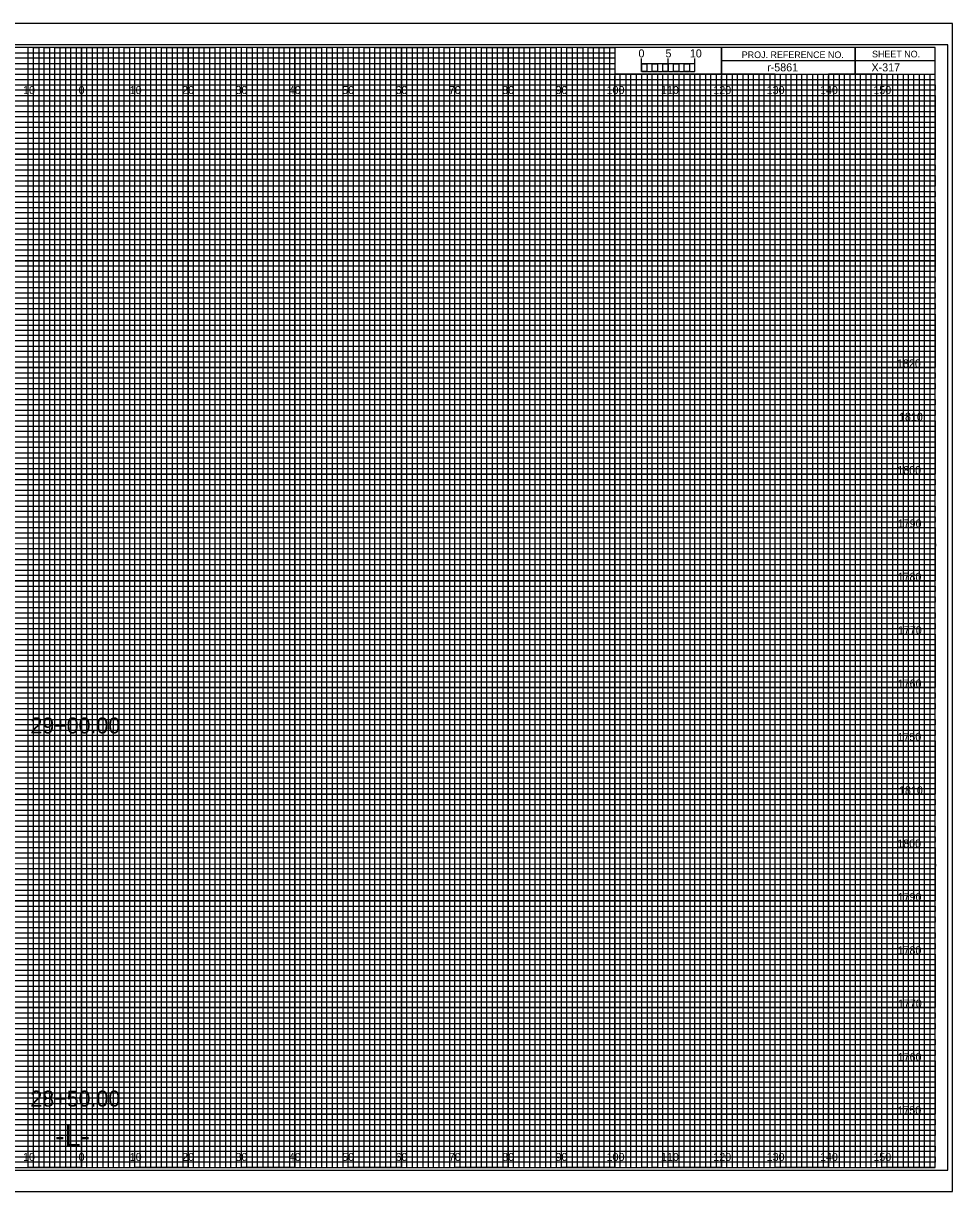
# Model space of a CAD drawing. Extents: x -15 to 323, y -5 to 6170.
# Drawn here: x 149.1 to 323.3, y 2855.5 to 3074.5 of the extents above; entities that cross this region are included whole.
import ezdxf

# ---------------------------------------------------------------- set-up
doc = ezdxf.new("R2010")
doc.units = 0
for name, color, linetype in [('Prop XS Alignment Label', 7, 'Continuous'), ('Prop XS Bar Scale Labels', 7, 'Continuous'), ('Prop XS DDE', 7, 'Continuous'), ('Prop XS DDE Earthwork Shape', 7, 'Continuous'), ('Prop XS DDE Slope Text', 7, 'Continuous'), ('Prop XS DDE Text', 7, 'Continuous'), ('Prop XS Earthwork Shape', 7, 'Continuous'), ('Prop XS Noise Wall', 7, 'Continuous'), ('Prop XS Project Number', 7, 'Continuous'), ('Prop XS Retaining Wall', 7, 'Continuous'), ('Prop XS Station Labels', 7, 'Continuous'), ('Prop XS Temporary Shoring', 7, 'Continuous'), ('Scratch_Level_3', 7, 'Continuous'), ('Scratch_Level_7', 7, 'Continuous'), ('Scratch_Level_8', 7, 'Continuous'), ('Sheet Cross Section Grid Minor 1 CELL', 7, 'Continuous')]:
    doc.layers.add(name, color=color, linetype=linetype)

msp = doc.modelspace()

# ---------------------------------------------------------------- linework, layer by layer
at = {"layer": 'Prop XS Alignment Label'}
for p, q in [((265, 3065.49), (265, 3067.9)), ((265, 3066.9), (265, 3067.9)), ((270, 3065.49), (270, 3067.9)), ((275, 3065.49), (275, 3067.9)), ((275, 3066.9), (275, 3067.9))]:
    msp.add_line(p, q, dxfattribs=at)
for points in [[(275, 3066.9), (265, 3066.9), (265, 3065.49), (275, 3065.49)], [(265, 3066.9), (266, 3066.9), (266, 3065.49), (265, 3065.49)], [(267, 3066.9), (268, 3066.9), (268, 3065.49), (267, 3065.49)], [(269, 3066.9), (270, 3066.9), (270, 3065.49), (269, 3065.49)], [(271, 3066.9), (272, 3066.9), (272, 3065.49), (271, 3065.49)], [(273, 3066.9), (274, 3066.9), (274, 3065.49), (273, 3065.49)]]:
    msp.add_lwpolyline(points, close=True, dxfattribs=at)
at = {"layer": 'Prop XS DDE'}
msp.add_lwpolyline([(-13.4, 2855.5), (323.3, 2855.5), (323.3, 3074.5), (-13.4, 3074.5)], close=True, dxfattribs=at)
at = {"layer": 'Prop XS DDE Slope Text'}
msp.add_lwpolyline([(-10.8, 2859.5), (322.4, 2859.5), (322.4, 3070.5), (-10.8, 3070.5)], close=True, dxfattribs=at)
at = {"layer": 'Prop XS DDE Text'}
for p, q in [((150, 2860), (150, 3070)), ((160, 2860), (160, 3070)), ((170, 2860), (170, 3070)), ((180, 2860), (180, 3070)), ((190, 2860), (190, 3070)), ((200, 2860), (200, 3070)), ((210, 2860), (210, 3070)), ((220, 2860), (220, 3070)), ((230, 2860), (230, 3070)), ((240, 2860), (240, 3070)), ((250, 2860), (250, 3070)), ((260, 2860), (260, 3064.69)), ((270, 2860), (270, 3064.69)), ((280, 2860), (280, 3064.69)), ((290, 2860), (290, 3064.69)), ((300, 2860), (300, 3064.69)), ((310, 2860), (310, 3064.69)), ((0, 3060), (320, 3060)), ((0, 3050), (320, 3050)), ((0, 3040), (320, 3040)), ((0, 3030), (320, 3030)), ((0, 3020), (320, 3020)), ((0, 3010), (320, 3010)), ((0, 3000), (320, 3000)), ((0, 2990), (320, 2990)), ((0, 2980), (320, 2980)), ((0, 2970), (320, 2970)), ((0, 2960), (320, 2960)), ((0, 2950), (320, 2950)), ((0, 2940), (320, 2940)), ((0, 2930), (320, 2930)), ((0, 2920), (320, 2920)), ((0, 2910), (320, 2910)), ((0, 2900), (320, 2900)), ((0, 2890), (320, 2890)), ((0, 2880), (320, 2880)), ((0, 2870), (320, 2870))]:
    msp.add_line(p, q, dxfattribs=at)
at = {"layer": 'Prop XS Earthwork Shape'}
for p, q in [((150, 3070), (140, 3070)), ((150, 2860), (150, 3070)), ((170, 3070), (160, 3070)), ((160, 3070), (160, 2860)), ((170, 2860), (170, 3070)), ((190, 3070), (180, 3070)), ((180, 3070), (180, 2860)), ((190, 2860), (190, 3070)), ((210, 3070), (200, 3070)), ((200, 3070), (200, 2860)), ((210, 2860), (210, 3070)), ((230, 3070), (220, 3070)), ((220, 3070), (220, 2860)), ((230, 2860), (230, 3070)), ((250, 3070), (240, 3070)), ((240, 3070), (240, 2860)), ((250, 2860), (250, 3070)), ((260, 3070), (260, 2860)), ((270, 2860), (270, 3065)), ((290, 3065), (280, 3065)), ((280, 3065), (280, 2860)), ((290, 2860), (290, 3065)), ((310, 3065), (300, 3065)), ((300, 3065), (300, 2860)), ((310, 2860), (310, 3065)), ((160, 2860), (150, 2860)), ((180, 2860), (170, 2860)), ((200, 2860), (190, 2860)), ((220, 2860), (210, 2860)), ((240, 2860), (230, 2860)), ((260, 2860), (250, 2860)), ((280, 2860), (270, 2860)), ((300, 2860), (290, 2860)), ((320, 2860), (310, 2860)), ((320, 2860), (320, 2860))]:
    msp.add_line(p, q, dxfattribs=at)
for points in [[(0, 3060), (320, 3060), (320, 3050), (0, 3050)], [(0, 3040), (320, 3040), (320, 3030), (0, 3030)], [(0, 3020), (320, 3020), (320, 3010), (0, 3010)], [(0, 3000), (320, 3000), (320, 2990), (0, 2990)], [(0, 2980), (320, 2980), (320, 2970), (0, 2970)], [(0, 2960), (320, 2960), (320, 2950), (0, 2950)], [(0, 2940), (320, 2940), (320, 2930), (0, 2930)], [(0, 2920), (320, 2920), (320, 2910), (0, 2910)], [(0, 2900), (320, 2900), (320, 2890), (0, 2890)], [(0, 2880), (320, 2880), (320, 2870), (0, 2870)]]:
    msp.add_lwpolyline(points, dxfattribs=at)
at = {"layer": 'Prop XS Noise Wall'}
for p, q in [((305, 3070), (305, 3065)), ((305, 3065), (305, 3070)), ((280, 3067.5), (280, 3065)), ((320, 3067.49), (280, 3067.49)), ((280, 3065), (320, 3065))]:
    msp.add_line(p, q, dxfattribs=at)
for points in [[(320, 3070), (0, 3070), (0, 2860), (320, 2860)], [(280, 3070), (260, 3070), (260, 3065.03), (280, 3065.03)], [(320, 3070), (280, 3070), (280, 3065), (320, 3065)]]:
    msp.add_lwpolyline(points, close=True, dxfattribs=at)
at = {"layer": 'Prop XS Retaining Wall'}
for p, q in [((267, 3065), (266.01, 3065)), ((266.01, 3065), (266.01, 2860)), ((267, 2860), (267, 3065)), ((269, 3065), (268, 3065)), ((268, 3065), (268, 2860)), ((269, 2860), (269, 3065)), ((266.01, 2860), (265, 2860)), ((268, 2860), (267, 2860))]:
    msp.add_line(p, q, dxfattribs=at)
for points in [[(150, 2860), (151, 2860), (151, 3070), (152, 3070), (152, 2860)], [(152, 2860), (153, 2860), (153, 3070), (154, 3070), (154, 2860)], [(155, 2860), (156, 2860), (156, 3070), (157, 3070), (157, 2860)], [(157, 2860), (158, 2860), (158, 3070), (159, 3070), (159, 2860)], [(160, 2860), (161, 2860), (161, 3070), (162, 3070), (162, 2860)], [(162, 2860), (163, 2860), (163, 3070), (164, 3070), (164, 2860)], [(165, 2860), (166, 2860), (166, 3070), (167, 3070), (167, 2860)], [(167, 2860), (168, 2860), (168, 3070), (169, 3070), (169, 2860)], [(170, 2860), (171, 2860), (171, 3070), (172, 3070), (172, 2860)], [(172, 2860), (173, 2860), (173, 3070), (174, 3070), (174, 2860)], [(175, 2860), (176, 2860), (176, 3070), (177, 3070), (177, 2860)], [(177, 2860), (178, 2860), (178, 3070), (179, 3070), (179, 2860)], [(180, 2860), (181, 2860), (181, 3070), (182, 3070), (182, 2860)], [(182, 2860), (183, 2860), (183, 3070), (184, 3070), (184, 2860)], [(185, 2860), (186, 2860), (186, 3070), (187, 3070), (187, 2860)], [(187, 2860), (188, 2860), (188, 3070), (189, 3070), (189, 2860)], [(190, 2860), (191, 2860), (191, 3070), (192, 3070), (192, 2860)], [(192, 2860), (193, 2860), (193, 3070), (194, 3070), (194, 2860)], [(195, 2860), (196, 2860), (196, 3070), (197, 3070), (197, 2860)], [(197, 2860), (198, 2860), (198, 3070), (199, 3070), (199, 2860)], [(200, 2860), (201, 2860), (201, 3070), (202, 3070), (202, 2860)], [(202, 2860), (203, 2860), (203, 3070), (204, 3070), (204, 2860)], [(205, 2860), (206, 2860), (206, 3070), (207, 3070), (207, 2860)], [(207, 2860), (208, 2860), (208, 3070), (209, 3070), (209, 2860)], [(210, 2860), (211, 2860), (211, 3070), (212, 3070), (212, 2860)], [(212, 2860), (213, 2860), (213, 3070), (214, 3070), (214, 2860)], [(215, 2860), (216, 2860), (216, 3070), (217, 3070), (217, 2860)], [(217, 2860), (218, 2860), (218, 3070), (219, 3070), (219, 2860)], [(220, 2860), (221, 2860), (221, 3070), (222, 3070), (222, 2860)], [(222, 2860), (223, 2860), (223, 3070), (224, 3070), (224, 2860)], [(225, 2860), (226, 2860), (226, 3070), (227, 3070), (227, 2860)], [(227, 2860), (228, 2860), (228, 3070), (229, 3070), (229, 2860)], [(230, 2860), (231, 2860), (231, 3070), (232, 3070), (232, 2860)], [(232, 2860), (233, 2860), (233, 3070), (234, 3070), (234, 2860)], [(235, 2860), (236, 2860), (236, 3070), (237, 3070), (237, 2860)], [(237, 2860), (238, 2860), (238, 3070), (239, 3070), (239, 2860)], [(240, 2860), (241, 2860), (241, 3070), (242, 3070), (242, 2860)], [(242, 2860), (243, 2860), (243, 3070), (244, 3070), (244, 2860)], [(245, 2860), (246, 2860), (246, 3070), (247, 3070), (247, 2860)], [(247, 2860), (248, 2860), (248, 3070), (249, 3070), (249, 2860)], [(250, 2860), (251, 2860), (251, 3070), (252, 3070), (252, 2860)], [(252, 2860), (253, 2860), (253, 3070), (254, 3070), (254, 2860)], [(255, 2860), (256, 2860), (256, 3070), (257, 3070), (257, 2860)], [(257, 2860), (258, 2860), (258, 3070), (259, 3070), (259, 2860)], [(260, 2860), (261, 2860), (261, 3065), (262.02, 3065), (262.02, 2860)], [(262, 2860), (263, 2860), (263, 3065), (263.99, 3065), (263.99, 2860)], [(270, 2860), (270.98, 2860), (270.98, 3065), (272, 3065), (272, 2860)], [(272, 2860), (273, 2860), (273, 3065), (274.05, 3065), (274.05, 2860)], [(275, 2860), (276, 2860), (276, 3065), (277, 3065), (277, 2860)], [(277, 2860), (278, 2860), (278, 3065), (279, 3065), (279, 2860)], [(280, 2860), (281, 2860), (281, 3065), (282, 3065), (282, 2860)], [(282, 2860), (283, 2860), (283, 3065), (284, 3065), (284, 2860)], [(285, 2860), (286, 2860), (286, 3065), (287, 3065), (287, 2860)], [(287, 2860), (288, 2860), (288, 3065), (289, 3065), (289, 2860)], [(290, 2860), (291, 2860), (291, 3065), (292, 3065), (292, 2860)], [(292, 2860), (293, 2860), (293, 3065), (294, 3065), (294, 2860)], [(295, 2860), (296, 2860), (296, 3065), (297, 3065), (297, 2860)], [(297, 2860), (298, 2860), (298, 3065), (299, 3065), (299, 2860)], [(300, 2860), (301, 2860), (301, 3065), (302, 3065), (302, 2860)], [(302, 2860), (303, 2860), (303, 3065), (304, 3065), (304, 2860)], [(305, 2860), (306, 2860), (306, 3065), (307, 3065), (307, 2860)], [(307, 2860), (308, 2860), (308, 3065), (309, 3065), (309, 2860)], [(310, 2860), (311, 2860), (311, 3065), (312, 3065), (312, 2860)], [(312, 2860), (313, 2860), (313, 3065), (314, 3065), (314, 2860)], [(315, 2860), (316, 2860), (316, 3065), (317, 3065), (317, 2860)], [(317, 2860), (318, 2860), (318, 3065), (319, 3065), (319, 2860)]]:
    msp.add_lwpolyline(points, dxfattribs=at)
at = {"layer": 'Prop XS Station Labels'}
for points in [[(145, 2860), (155, 2860), (155, 3070), (165, 3070), (165, 2860), (175, 2860), (175, 3070), (185, 3070), (185, 2860), (195, 2860), (195, 3070), (205, 3070), (205, 2860), (215, 2860), (215, 3070), (225, 3070), (225, 2860), (235, 2860), (235, 3070), (245, 3070), (245, 2860), (255, 2860), (255, 3070), (259.93, 3070), (260, 3070), (260, 3065), (264.99, 3065), (264.99, 2860), (275, 2860), (275, 3065), (285, 3065), (285, 2860), (295, 2860), (295, 3065), (305, 3065), (305, 2860), (315, 2860), (315, 3065)], [(0, 3065), (275, 3065)], [(0, 3045), (320, 3045), (320, 3055), (0, 3055)], [(0, 3025), (320, 3025), (320, 3035), (0, 3035)], [(0, 3005), (320, 3005), (320, 3015), (0, 3015)], [(0, 2985), (320, 2985), (320, 2995), (0, 2995)], [(0, 2965), (320, 2965), (320, 2975), (0, 2975)], [(0, 2945), (320, 2945), (320, 2955), (0, 2955)], [(0, 2925), (320, 2925), (320, 2935), (0, 2935)], [(0, 2905), (320, 2905), (320, 2915), (0, 2915)], [(0, 2885), (320, 2885), (320, 2895), (0, 2895)], [(0, 2865), (320, 2865), (320, 2875), (0, 2875)]]:
    msp.add_lwpolyline(points, dxfattribs=at)
at = {"layer": 'Scratch_Level_7'}
for p, q in [((323.3, 3074.5), (-13.4, 3074.5)), ((-13.4, 2855.5), (323.3, 2855.5))]:
    msp.add_line(p, q, dxfattribs=at)
at = {"layer": 'Sheet Cross Section Grid Minor 1 CELL'}
for p, q in [((0, 3069), (260, 3069)), ((260, 3069), (260, 3067.98)), ((260, 3067.98), (0, 3067.98)), ((0, 3067), (260, 3067)), ((260, 3067), (260, 3065.89)), ((260, 3065.89), (0, 3065.89)), ((0, 3064), (320, 3064))]:
    msp.add_line(p, q, dxfattribs=at)
for points in [[(0, 3063), (270, 3063), (320, 3063), (320, 3062), (0, 3062)], [(0, 3061), (320, 3061), (320, 3059), (0, 3059)], [(0, 3058), (320, 3058), (320, 3057), (0, 3056.98)], [(0, 3056), (320, 3056), (320, 3054), (0, 3054)], [(0, 3053), (320, 3053), (320, 3052), (0, 3052)], [(0, 3051), (320, 3051), (320, 3049), (0, 3049)], [(0, 3048), (320, 3048), (320, 3047), (0, 3047)], [(0, 3046), (320, 3046), (320, 3044), (0, 3044)], [(0, 3043), (320, 3043), (320, 3042), (0, 3042)], [(0, 3041), (320, 3041), (320, 3039), (0, 3039)], [(0, 3038), (320, 3038), (320, 3037), (0, 3037)], [(0, 3036), (320, 3036), (320, 3033.95), (320, 3033), (320, 3032), (0, 3032)], [(0, 3034), (320, 3034), (320, 3033), (0, 3033)], [(0, 3031), (320, 3031), (320, 3029), (0, 3029.03)], [(0, 3029.03), (320, 3029), (320, 3028), (0, 3028)], [(0, 3027), (320, 3027), (320, 3026), (0, 3026)], [(0, 3024), (320, 3024), (320, 3023), (0, 3023)], [(0, 3022), (320, 3022), (320, 3021), (0, 3021)], [(-0.07, 3018.89), (320, 3018.89), (320, 3017.88), (-0.07, 3017.88)], [(0, 3017), (320, 3017), (320, 3016), (0, 3016)], [(0, 3014), (320, 3014), (320, 3013), (0, 3013)], [(0, 3012), (320, 3012), (320, 3011), (0, 3011)], [(0, 3009), (320, 3009), (320, 3008), (0, 3008)], [(0, 3007), (320, 3007), (320, 3006), (0, 3006)], [(0, 3004), (320, 3004), (320, 3003), (0, 3003)], [(0, 3002), (320, 3002), (320, 3001), (0, 3001)], [(0, 2999), (320, 2999), (319.99, 2997.98), (0, 2998)], [(0, 2997), (320, 2997), (320, 2996), (0, 2996)], [(0, 2994), (320, 2994), (320, 2993), (0, 2993)], [(0, 2992), (320, 2992), (320, 2991), (0, 2991)], [(0, 2989), (320, 2989), (320, 2988), (0, 2988)], [(0, 2987), (320, 2987), (320, 2986), (0, 2986)], [(0, 2984), (320, 2984), (320, 2983), (0, 2983)], [(0, 2982), (320, 2982), (320, 2981), (0, 2981)], [(0, 2979), (320, 2979), (320, 2978), (0, 2978)], [(0, 2976.99), (320.07, 2976.91), (320, 2976), (0, 2976)], [(0, 2974), (320, 2974), (320, 2973), (0, 2973)], [(0, 2972), (320, 2972), (320, 2971), (0, 2971)], [(0, 2969), (320, 2969), (320, 2968), (0, 2968)], [(0, 2967), (320, 2967), (320, 2966), (0, 2966)], [(0, 2964), (320, 2964), (320, 2963), (0, 2963)], [(0, 2962), (320, 2962), (320, 2961), (0, 2961)], [(0, 2959), (320, 2959), (320, 2958), (0, 2958)], [(0, 2957), (320, 2957), (320, 2956), (0, 2956)], [(0, 2954), (320, 2954), (320, 2953), (0, 2953)], [(0, 2952), (320, 2952), (320, 2951), (0, 2951)], [(0, 2949), (320, 2949), (320, 2948), (0, 2948)], [(0, 2947), (320, 2947), (320, 2946), (0, 2946)], [(0, 2944), (320, 2944), (320, 2943), (0, 2943)], [(0, 2942), (320, 2942), (320, 2941), (0, 2941)], [(0, 2939), (320, 2939), (319.99, 2937.98), (0, 2938)], [(0, 2937), (320, 2937), (320, 2936), (0, 2936)], [(0, 2934), (320, 2934), (320, 2933), (0, 2933)], [(0, 2932), (320, 2932), (320, 2931), (0, 2931)], [(0, 2929), (320, 2929), (320, 2928), (0, 2928)], [(0, 2927), (320, 2927), (320, 2926), (0, 2926)], [(0, 2924), (320, 2924), (320, 2923), (0, 2923)], [(0, 2922), (320, 2922), (320, 2921), (0, 2921)], [(0, 2919), (320, 2919), (320, 2918), (0, 2918)], [(0, 2916.99), (320.07, 2916.91), (320, 2916), (0, 2916)], [(0, 2914), (320, 2914), (320, 2913), (0, 2913)], [(0, 2912), (320, 2912), (320, 2911), (0, 2911)], [(0, 2909), (320, 2909), (320, 2908), (0, 2908)], [(0, 2907), (320, 2907), (320, 2906), (0, 2906)], [(0, 2904), (320, 2904), (320, 2903), (0, 2903)], [(0, 2902), (320, 2902), (320, 2901), (0, 2901)], [(0, 2899), (320, 2899), (320, 2898), (0, 2898)], [(0, 2897), (320, 2897), (320, 2896), (0, 2896)], [(0, 2894), (320, 2894), (320, 2893), (0, 2893)], [(0, 2892), (320, 2892), (320, 2891), (0, 2891)], [(0, 2889), (320, 2889), (320, 2888), (0, 2888)], [(0, 2887), (320, 2887), (320, 2886), (0, 2886)], [(0, 2884), (320, 2884), (320, 2883), (0, 2883)], [(0, 2882), (320, 2882), (320, 2881), (0, 2881)], [(0, 2879), (320, 2879), (320, 2878), (0, 2878)], [(0, 2877), (320, 2877), (320, 2876), (0, 2876)], [(0, 2874), (320, 2874), (320, 2873), (0, 2873)], [(0, 2872), (320, 2872), (320, 2871), (0, 2871)], [(0, 2869), (320, 2869), (320, 2868), (0, 2868)], [(0, 2867), (320, 2867), (320, 2866), (0, 2866)], [(0, 2864), (320, 2864), (320, 2863), (0, 2863)], [(0, 2862), (320, 2862), (320, 2861), (0, 2861)]]:
    msp.add_lwpolyline(points, dxfattribs=at)

# ---------------------------------------------------------------- texts
at = {"layer": 'Prop XS Alignment Label'}
for s, height, p in [('0', 1.5, (264.41, 3068.12)), ('-L-', 4, (155.06, 2864))]:
    msp.add_text(s, height=height, dxfattribs=at).set_placement(p)
at = {"layer": 'Prop XS Bar Scale Labels'}
for s, p in [('5', (269.47, 3068.12)), ('10', (274.04, 3068.12))]:
    msp.add_text(s, height=1.5, dxfattribs=at).set_placement(p)
at = {"layer": 'Prop XS DDE Earthwork Shape'}
msp.add_text('X-317', height=1.5, dxfattribs=at).set_placement((308.09, 3065.5))
at = {"layer": 'Prop XS Noise Wall'}
for s, p in [('PROJ. REFERENCE NO.', (283.77, 3067.99)), ('SHEET NO.', (308.19, 3068.12))]:
    msp.add_text(s, height=1.25, dxfattribs=at).set_placement(p)
at = {"layer": 'Prop XS Project Number'}
msp.add_text('r-5861', height=1.5, dxfattribs=at).set_placement((288.53, 3065.5))
at = {"layer": 'Prop XS Temporary Shoring'}
for s, p in [('29+00.00', (150.41, 2941.39)), ('28+50.00', (150.41, 2871.44))]:
    msp.add_text(s, height=3, dxfattribs=at).set_placement(p)
at = {"layer": 'Scratch_Level_3'}
for s, p in [('1820', (312.87, 3010)), ('1810', (313.25, 3000)), ('1800', (312.92, 2990)), ('1790', (313, 2980)), ('1780', (312.98, 2970)), ('1770', (313.04, 2960)), ('1760', (313, 2950)), ('1750', (312.96, 2940)), ('1810', (313.25, 2930)), ('1800', (312.92, 2920)), ('1790', (313, 2910)), ('1780', (312.98, 2900)), ('1770', (313.04, 2890)), ('1760', (313, 2880)), ('1750', (312.96, 2870))]:
    msp.add_text(s, height=1.5, dxfattribs=at).set_placement(p)
at = {"layer": 'Scratch_Level_8'}
for s, p in [('10', (149.04, 3061.25)), ('0', (159.45, 3061.25)), ('0', (159.45, 3061.25)), ('10', (169.04, 3061.25)), ('20', (178.86, 3061.25)), ('30', (188.86, 3061.25)), ('40', (198.86, 3061.25)), ('50', (208.86, 3061.25)), ('60', (218.86, 3061.25)), ('70', (228.86, 3061.25)), ('80', (238.86, 3061.25)), ('90', (248.86, 3061.25)), ('100', (258.44, 3061.25)), ('110', (268.62, 3061.25)), ('120', (278.44, 3061.25)), ('130', (288.44, 3061.25)), ('140', (298.44, 3061.25)), ('150', (308.44, 3061.25)), ('10', (149.04, 2861.25)), ('0', (159.45, 2861.25)), ('0', (159.45, 2861.25)), ('10', (169.04, 2861.25)), ('20', (178.86, 2861.25)), ('30', (188.86, 2861.25)), ('40', (198.86, 2861.25)), ('50', (208.86, 2861.25)), ('60', (218.86, 2861.25)), ('70', (228.86, 2861.25)), ('80', (238.86, 2861.25)), ('90', (248.86, 2861.25)), ('100', (258.44, 2861.25)), ('110', (268.62, 2861.25)), ('120', (278.44, 2861.25)), ('130', (288.44, 2861.25)), ('140', (298.44, 2861.25)), ('150', (308.44, 2861.25))]:
    msp.add_text(s, height=1.5, dxfattribs=at).set_placement(p)

doc.saveas('drawing.dxf')
